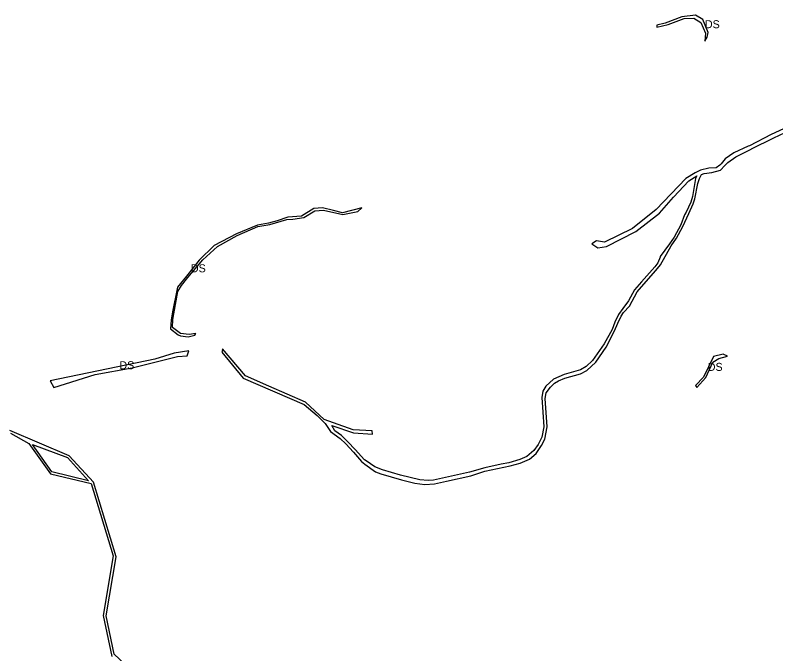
# Model space of a CAD drawing. Extents: x -477304 to -465641, y -1159113 to -1149285.
# Drawn here: x -470581 to -469726, y -1157703 to -1156985 of the extents above; entities that cross this region are included whole.
import ezdxf

# ---------------------------------------------------------------- set-up
doc = ezdxf.new("R2010")
doc.units = 0
doc.layers.add('35', color=7, linetype='Continuous')

msp = doc.modelspace()

# ---------------------------------------------------------------- linework, layer by layer
at = {"layer": '35'}
for p, q in [((-469829.17, -1156988.96), (-469818.32, -1156988.64)), ((-469818.32, -1156988.64), (-469810.29, -1156993.49)), ((-469850.41, -1156994.54), (-469859.82, -1156996.46)), ((-469859.82, -1156996.46), (-469859.61, -1156998.8)), ((-469805.82, -1157014.69), (-469803.27, -1157010.03)), ((-469731.27, -1157119.42), (-469755.59, -1157132.11)), ((-469755.59, -1157132.11), (-469756.98, -1157132.75)), ((-469771.08, -1157144.46), (-469753.76, -1157135.98)), ((-469753.76, -1157135.98), (-469753.2, -1157135.7)), ((-469810.64, -1157159.49), (-469816.75, -1157162.46)), ((-469814.72, -1157165.92), (-469816.25, -1157168.72)), ((-469813.54, -1157174.62), (-469811.95, -1157168.92)), ((-469811.95, -1157168.92), (-469809.39, -1157164.35)), ((-469809.39, -1157164.35), (-469806.51, -1157163.44)), ((-469806.51, -1157163.44), (-469798.07, -1157162.08)), ((-469816.88, -1157191.87), (-469813.54, -1157174.62)), ((-469856.77, -1157207.95), (-469840.92, -1157189.8)), ((-469818.93, -1157197.53), (-469816.88, -1157191.87)), ((-470191.49, -1157202.04), (-470213.31, -1157207.49)), ((-470195.96, -1157205.84), (-470191.49, -1157202.04)), ((-469821.61, -1157195.4), (-469826.9, -1157206.75)), ((-470213.31, -1157207.49), (-470223.27, -1157204.9)), ((-469883.54, -1157228.36), (-469856.77, -1157207.95)), ((-469828.52, -1157209.69), (-469832.82, -1157221.07)), ((-469826.9, -1157206.75), (-469828.52, -1157209.69)), ((-470294.88, -1157220.53), (-470275.77, -1157214.84)), ((-470275.77, -1157214.84), (-470268.99, -1157214.5)), ((-470268.99, -1157214.5), (-470256.89, -1157212.88)), ((-469887.26, -1157224.97), (-469918.51, -1157240.52)), ((-469832.82, -1157221.07), (-469840.32, -1157234.69)), ((-470354.01, -1157245.37), (-470331.82, -1157233.04)), ((-470357.76, -1157244.05), (-470374.38, -1157260.79)), ((-469932.83, -1157242.25), (-469926, -1157246.84)), ((-469855.52, -1157265.75), (-469843.78, -1157244.72)), ((-470374.38, -1157260.79), (-470388.8, -1157278.63)), ((-469860.88, -1157272.17), (-469855.52, -1157265.75)), ((-470388.8, -1157278.63), (-470398.85, -1157291.12)), ((-470394.45, -1157289.02), (-470387.1, -1157280.12)), ((-469876.89, -1157284.97), (-469884.89, -1157293.99)), ((-470398.85, -1157291.12), (-470404.33, -1157318.84)), ((-469884.89, -1157293.99), (-469891.59, -1157306.19)), ((-469897.1, -1157319.56), (-469890.58, -1157312.27)), ((-469902.94, -1157321.61), (-469906.88, -1157330.25)), ((-469899.99, -1157323.63), (-469897.1, -1157319.56)), ((-470404.25, -1157336.33), (-470403.92, -1157327.24)), ((-469906.88, -1157330.25), (-469910.02, -1157338.5)), ((-469903.68, -1157331.6), (-469899.99, -1157323.63)), ((-470406.52, -1157337.77), (-470398.06, -1157344.53)), ((-470395.61, -1157343.21), (-470404.25, -1157336.33)), ((-470398.06, -1157344.53), (-470395.41, -1157345.58)), ((-470385.86, -1157344.09), (-470395.61, -1157343.21)), ((-470395.41, -1157345.58), (-470386.91, -1157346.93)), ((-470386.91, -1157346.93), (-470379.16, -1157344.91)), ((-470378.33, -1157343.06), (-470385.86, -1157344.09)), ((-470379.16, -1157344.91), (-470378.33, -1157343.06)), ((-470402.65, -1157365.26), (-470424.28, -1157371.82)), ((-470386.16, -1157362.62), (-470402.65, -1157365.26)), ((-470387.82, -1157368.04), (-470386.16, -1157362.62)), ((-470348.24, -1157360.32), (-470348.7, -1157363.23)), ((-470322.4, -1157390.7), (-470348.24, -1157360.32)), ((-470424.28, -1157371.82), (-470542.1, -1157396.43)), ((-469780.15, -1157368.63), (-469785.33, -1157366.45)), ((-469938.56, -1157384.71), (-469928.36, -1157375.39)), ((-470295.96, -1157402.26), (-470322.4, -1157390.7)), ((-469963.95, -1157389.27), (-469975.82, -1157394.57)), ((-469945.74, -1157388.35), (-469938.56, -1157384.71)), ((-470542.1, -1157396.43), (-470538.02, -1157403.81)), ((-469979.32, -1157403.21), (-469974.78, -1157399.04)), ((-469807.24, -1157392.28), (-469816.1, -1157401.51)), ((-469984.29, -1157409.57), (-469979.32, -1157403.21)), ((-469985.45, -1157416.11), (-469984.29, -1157409.57)), ((-470241.79, -1157435.27), (-470232.79, -1157444.24)), ((-470223.56, -1157443.33), (-470233.98, -1157439.55)), ((-470232.79, -1157444.24), (-470227.48, -1157451.94)), ((-470222.04, -1157452.57), (-470225.27, -1157446.55)), ((-470225.27, -1157446.55), (-470201.02, -1157454.7)), ((-470201.08, -1157451.18), (-470223.56, -1157443.33)), ((-470180.05, -1157452.61), (-470201.08, -1157451.18)), ((-470227.48, -1157451.94), (-470226.71, -1157453.07)), ((-470226.71, -1157453.07), (-470215.81, -1157460.98)), ((-470201.02, -1157454.7), (-470179.42, -1157456.13)), ((-470179.42, -1157456.13), (-470180.05, -1157452.61)), ((-470188.55, -1157484.88), (-470199.07, -1157473.54)), ((-469997.97, -1157474.45), (-470005.84, -1157481.4)), ((-470522.63, -1157482.44), (-470498.74, -1157508.47)), ((-470186.73, -1157486.12), (-470188.55, -1157484.88)), ((-470005.84, -1157481.4), (-470013.77, -1157484.69)), ((-470176.85, -1157492.88), (-470186.73, -1157486.12)), ((-470498.74, -1157508.47), (-470540.24, -1157498.37)), ((-470146.88, -1157507.34), (-470132.05, -1157511.33)), ((-470110.81, -1157507.77), (-470116.78, -1157508.3)), ((-470096.22, -1157508.83), (-470068.98, -1157502.9)), ((-470479.19, -1157660.29), (-470467.8, -1157593.84))]:
    msp.add_line(p, q, dxfattribs=at)
for points in [[(-469859.61, -1156998.8), (-469847.05, -1156995.87), (-469829.17, -1156988.96)], [(-469816.15, -1156985.43), (-469831.75, -1156987.4), (-469850.41, -1156994.54)], [(-469803.27, -1157010.03), (-469801.88, -1157004.84), (-469808.1, -1156990.24), (-469816.15, -1156985.43)], [(-469810.29, -1156993.49), (-469805.17, -1157005.62), (-469805.82, -1157014.69)], [(-469694.82, -1157103.19), (-469717.23, -1157113.19), (-469731.27, -1157119.42)], [(-469753.2, -1157135.7), (-469728.32, -1157123.1), (-469715.43, -1157117.07)], [(-469756.98, -1157132.75), (-469773.25, -1157139.89), (-469782.97, -1157146.79), (-469787.48, -1157152.6), (-469789.07, -1157153.76), (-469793.21, -1157156.78), (-469801.43, -1157157.29), (-469810.64, -1157159.49)], [(-469798.07, -1157162.08), (-469788.22, -1157159.71), (-469783.29, -1157154.37), (-469780.08, -1157150.78), (-469771.08, -1157144.46)], [(-469816.75, -1157162.46), (-469826.99, -1157168.9), (-469860.45, -1157203.65), (-469887.26, -1157224.97)], [(-469840.92, -1157189.8), (-469823.76, -1157171.58), (-469814.72, -1157165.92)], [(-469816.25, -1157168.72), (-469819.7, -1157189.19), (-469821.61, -1157195.4)], [(-470245.64, -1157202.75), (-470259.49, -1157211.18), (-470274.84, -1157212.36), (-470286.62, -1157216.46)], [(-470223.27, -1157204.9), (-470235.67, -1157201.68), (-470245.64, -1157202.75)], [(-469843.78, -1157244.72), (-469837.53, -1157235.85), (-469830.53, -1157222.99), (-469823.95, -1157208.17), (-469818.93, -1157197.53)], [(-470256.89, -1157212.88), (-470244.39, -1157205.12), (-470234.76, -1157204.62)], [(-470234.76, -1157204.62), (-470212.91, -1157209.36), (-470195.96, -1157205.84)], [(-470286.62, -1157216.46), (-470296.42, -1157219.27), (-470308.69, -1157221.48), (-470332.55, -1157231.11), (-470357.76, -1157244.05)], [(-470331.82, -1157233.04), (-470308.43, -1157222.93), (-470294.88, -1157220.53)], [(-469926, -1157246.84), (-469916.41, -1157245.4), (-469883.54, -1157228.36)], [(-469840.32, -1157234.69), (-469845.54, -1157242.38), (-469856, -1157256.41)], [(-470387.1, -1157280.12), (-470370.48, -1157260.41), (-470354.01, -1157245.37)], [(-469918.51, -1157240.52), (-469927.59, -1157239.03), (-469932.83, -1157242.25)], [(-469856, -1157256.41), (-469855.99, -1157257.39), (-469858.8, -1157263.58)], [(-469858.8, -1157263.58), (-469862.1, -1157268.21), (-469876.89, -1157284.97)], [(-469890.58, -1157312.27), (-469881.88, -1157296.24), (-469874.56, -1157287.79), (-469860.88, -1157272.17)], [(-470403.92, -1157327.24), (-470398.47, -1157296.02), (-470394.45, -1157289.02)], [(-469891.59, -1157306.19), (-469897.99, -1157315.15), (-469902.94, -1157321.61)], [(-470404.33, -1157318.84), (-470405.99, -1157328.22), (-470406.52, -1157337.77)], [(-469928.36, -1157375.39), (-469916.68, -1157358.38), (-469907.19, -1157340.14), (-469903.68, -1157331.6)], [(-469910.02, -1157338.5), (-469919.12, -1157354.86), (-469932.26, -1157373.35), (-469939.28, -1157380.28)], [(-470348.7, -1157363.23), (-470348.98, -1157364.13), (-470325.13, -1157393.4), (-470256.43, -1157422.75), (-470241.79, -1157435.27)], [(-470538.02, -1157403.81), (-470491.32, -1157389.24), (-470449.82, -1157381.73), (-470398.69, -1157368.79), (-470387.82, -1157368.04)], [(-469785.33, -1157366.45), (-469796.15, -1157369.02), (-469807.24, -1157392.28)], [(-469796.88, -1157375.3), (-469789.95, -1157371.17), (-469780.15, -1157368.63)], [(-469939.28, -1157380.28), (-469945.63, -1157383.76), (-469963.95, -1157389.27)], [(-469816.1, -1157401.51), (-469814.93, -1157403.71), (-469804.48, -1157392.48), (-469796.88, -1157375.3)], [(-469974.78, -1157399.04), (-469970.45, -1157396.3), (-469963.05, -1157393.31), (-469945.74, -1157388.35)], [(-469975.82, -1157394.57), (-469984.54, -1157402.14), (-469987.8, -1157407.96), (-469989.12, -1157415.02)], [(-470233.98, -1157439.55), (-470254.78, -1157420.27), (-470295.96, -1157402.26)], [(-469989.12, -1157415.02), (-469986.81, -1157447.88), (-469989, -1157459.37), (-469993.1, -1157467.7), (-469997.97, -1157474.45)], [(-469985.75, -1157461.85), (-469983.07, -1157448.02), (-469985.45, -1157416.11)], [(-470467.8, -1157593.84), (-470493.17, -1157510.22), (-470520.62, -1157480.36), (-470587.46, -1157451.93)], [(-470586.63, -1157455.18), (-470565.87, -1157466.83), (-470541.6, -1157500.7)], [(-470199.07, -1157473.54), (-470207.31, -1157464.93), (-470214.51, -1157457.85), (-470222.04, -1157452.57)], [(-470540.24, -1157498.37), (-470561.99, -1157467.73), (-470522.63, -1157482.44)], [(-470215.81, -1157460.98), (-470209.33, -1157467.02), (-470200.77, -1157476.39)], [(-469995.51, -1157477.92), (-469989.35, -1157468.89), (-469985.75, -1157461.85)], [(-470200.77, -1157476.39), (-470191.71, -1157487), (-470188.22, -1157489.76)], [(-470068.98, -1157502.9), (-470053.13, -1157497.79), (-470024.55, -1157491.71), (-470013.36, -1157488.67), (-470002.9, -1157484.39), (-469995.51, -1157477.92)], [(-470013.77, -1157484.69), (-470026.09, -1157488.36), (-470034.85, -1157489.94), (-470053.12, -1157493.98)], [(-470188.22, -1157489.76), (-470176.26, -1157498.68), (-470170.27, -1157500.63), (-470146.88, -1157507.34)], [(-470147.99, -1157502.27), (-470168.43, -1157496.28), (-470176.85, -1157492.88)], [(-470053.12, -1157493.98), (-470070.58, -1157499.06), (-470110.81, -1157507.77)], [(-470541.6, -1157500.7), (-470495.79, -1157511.61), (-470471.1, -1157592.86)], [(-470116.78, -1157508.3), (-470126.39, -1157507.56), (-470147.99, -1157502.27)], [(-470132.05, -1157511.33), (-470120.81, -1157512.86), (-470109.8, -1157511.89), (-470096.22, -1157508.83)], [(-470471.1, -1157592.86), (-470482.49, -1157659.77), (-470472.59, -1157706.14)], [(-470435.1, -1157735.94), (-470470.19, -1157703.49), (-470479.19, -1157660.29)]]:
    msp.add_lwpolyline(points, dxfattribs=at)

# ---------------------------------------------------------------- texts
for p in [(-469805.72, -1157000.06), (-470383.75, -1157274.3), (-470464.13, -1157383.22), (-469802.51, -1157385.08)]:
    msp.add_text('DS', height=9, dxfattribs=at).set_placement(p)

doc.saveas('drawing.dxf')
